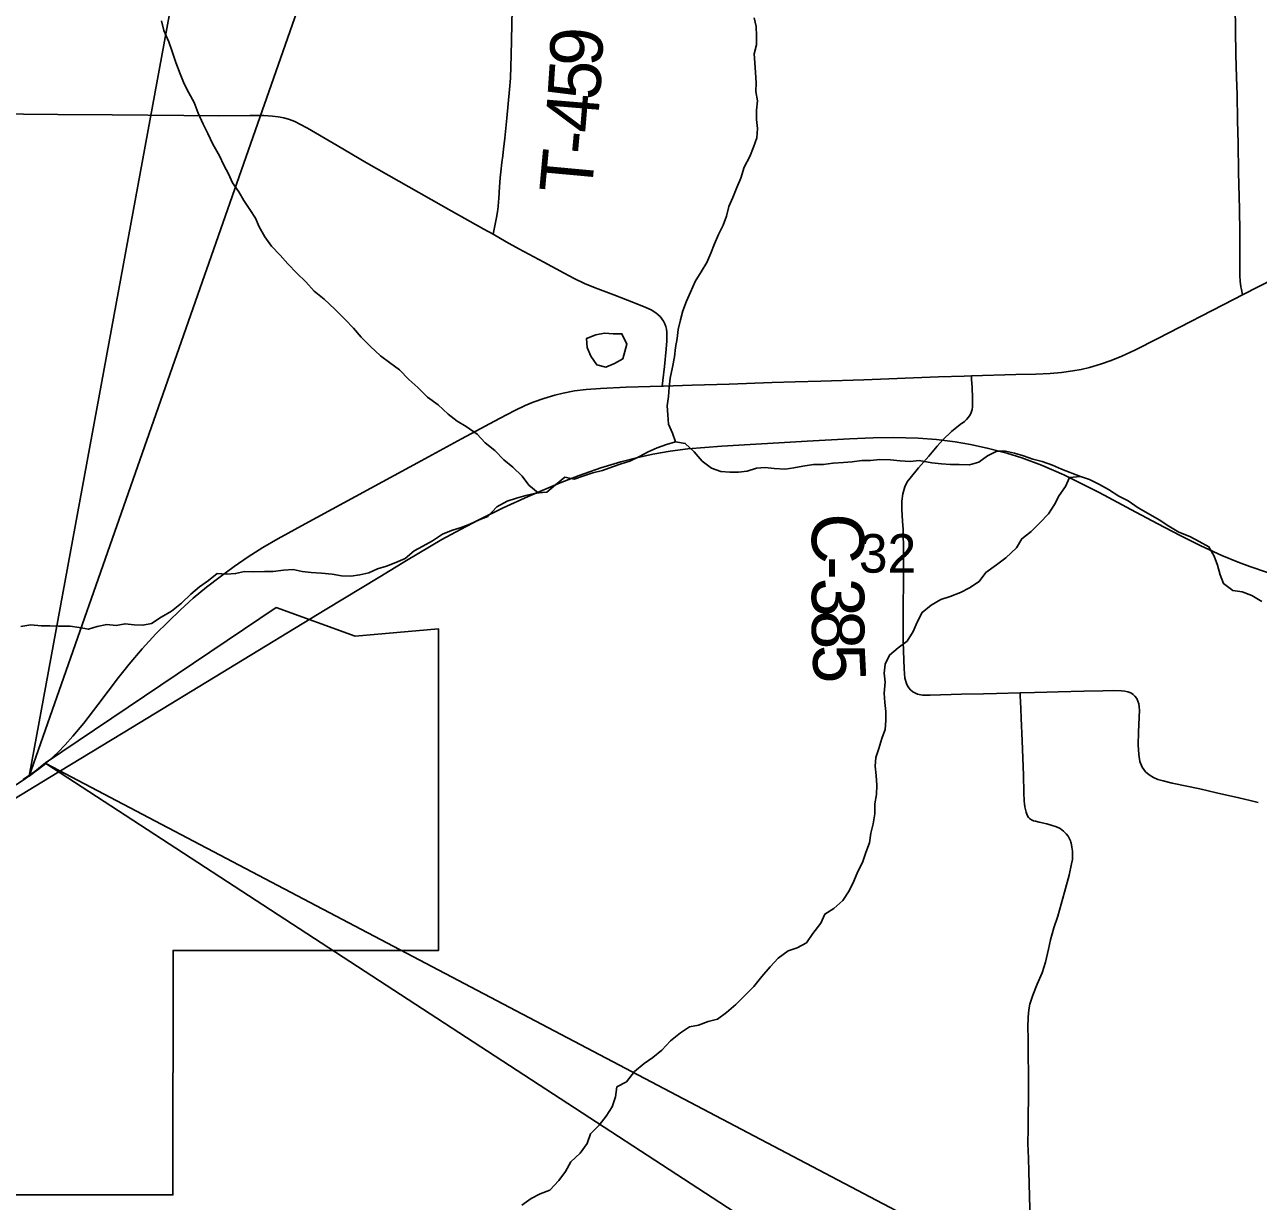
# Model space of a CAD drawing. Extents: x -7.5 to 53.5, y 0 to 22.
# Drawn here: x 5.246 to 6.583, y 17.086 to 18.362 of the extents above; entities that cross this region are included whole.
import ezdxf

# ---------------------------------------------------------------- set-up
doc = ezdxf.new("R2010")
doc.units = 0
for name, color, linetype in [('GM_X_Corporation', 7, 'Continuous'), ('GM_X_County_Road', 7, 'Continuous'), ('GM_X_County_Road_Text', 7, 'Continuous'), ('GM_X_Minor_Lake', 7, 'Continuous'), ('GM_X_Minor_River', 7, 'Continuous'), ('GM_X_Rail_Line', 7, 'Continuous'), ('GM_X_Section_Text', 7, 'Continuous'), ('GM_X_State_Route', 7, 'Continuous'), ('GM_X_Township_Road', 7, 'Continuous'), ('GM_X_Township_Road_Text', 7, 'Continuous'), ('SH_Data', 7, 'Continuous'), ('SH_Text', 7, 'Continuous')]:
    doc.layers.add(name, color=color, linetype=linetype)

msp = doc.modelspace()

# ---------------------------------------------------------------- linework, layer by layer
at = {"layer": 'GM_X_Corporation'}
msp.add_lwpolyline([(5.244, 17.5434), (5.2567, 17.5523), (5.2607, 17.5554), (5.2684, 17.5616), (5.5185, 17.73), (5.6039, 17.6989), (5.6945, 17.7068), (5.6945, 17.3582), (5.4066, 17.3583), (5.4065, 17.093), (5.1262, 17.0931)], dxfattribs=at)
at = {"layer": 'GM_X_County_Road'}
for points in [[(6.2722, 17.9813), (6.2724, 17.9775), (6.2729, 17.9691), (6.2734, 17.9571), (6.2734, 17.9508), (6.2733, 17.9477), (6.2728, 17.9447), (6.272, 17.9417), (6.2707, 17.9389), (6.269, 17.9364), (6.267, 17.934), (6.2648, 17.9317), (6.2599, 17.9284), (6.2506, 17.9211), (6.2413, 17.912), (6.2352, 17.9049), (6.226, 17.8942), (6.2149, 17.8815), (6.2057, 17.8705), (6.2025, 17.8664), (6.1998, 17.8611), (6.1977, 17.8532), (6.1969, 17.8454), (6.1969, 17.8365), (6.1974, 17.8238), (6.198, 17.8147), (6.1983, 17.8058), (6.1985, 17.7999), (6.1986, 17.7935), (6.1987, 17.7825), (6.1986, 17.7682), (6.1984, 17.7536), (6.1982, 17.7356), (6.198, 17.7181), (6.1982, 17.6928), (6.1992, 17.6636), (6.1999, 17.6536), (6.2016, 17.6477), (6.2029, 17.6452), (6.2044, 17.6429), (6.2061, 17.6409), (6.2087, 17.6386), (6.2138, 17.636), (6.219, 17.6352), (6.2274, 17.6349), (6.2614, 17.6362), (6.2851, 17.6366), (6.2992, 17.6369), (6.3251, 17.6374)], [(6.3251, 17.6374), (6.3407, 17.6378), (6.3539, 17.6382), (6.3662, 17.6385), (6.3942, 17.6392), (6.4147, 17.6398), (6.426, 17.6401), (6.4347, 17.6397), (6.4384, 17.6395), (6.4417, 17.6387), (6.4449, 17.6375), (6.4476, 17.6358), (6.4495, 17.634), (6.4514, 17.6313), (6.4527, 17.6286), (6.4537, 17.6257), (6.4541, 17.6224), (6.4543, 17.6188), (6.4539, 17.6112), (6.4532, 17.5948), (6.453, 17.5812), (6.4537, 17.5707), (6.4546, 17.5632), (6.4571, 17.557), (6.461, 17.552), (6.465, 17.5488), (6.4694, 17.5458), (6.4744, 17.5436), (6.4799, 17.542), (6.4899, 17.5397), (6.5197, 17.5334), (6.5378, 17.5292), (6.5621, 17.5237), (6.5742, 17.5209), (6.5832, 17.5188)]]:
    msp.add_lwpolyline(points, dxfattribs=at)
at = {"layer": 'GM_X_Minor_Lake'}
for points in [[(5.8742, 18.0275), (5.8648, 18.0257), (5.8549, 18.022), (5.8555, 18.0121), (5.8596, 18.0026), (5.866, 17.9931), (5.8758, 17.9907), (5.8853, 17.9948), (5.8941, 17.9996)], [(5.8941, 17.9996), (5.8984, 18.0155), (5.8932, 18.027), (5.8837, 18.027), (5.8742, 18.0275)]]:
    msp.add_lwpolyline(points, dxfattribs=at)
at = {"layer": 'GM_X_Minor_River'}
for points in [[(5.3942, 18.3663), (5.3967, 18.3557), (5.4019, 18.3435), (5.4056, 18.3329), (5.4097, 18.3211), (5.4142, 18.3089), (5.4186, 18.2979), (5.4238, 18.2883), (5.4294, 18.2777), (5.4339, 18.2662), (5.4391, 18.2541), (5.4443, 18.2441), (5.4499, 18.2327), (5.457, 18.2198), (5.4615, 18.2099), (5.4667, 18.2003), (5.4712, 18.1908), (5.4779, 18.1809), (5.4835, 18.1714), (5.4899, 18.1618), (5.4959, 18.1523), (5.5, 18.1428), (5.5063, 18.1321), (5.5134, 18.1218), (5.5228, 18.1122), (5.5311, 18.1027), (5.5409, 18.0927), (5.5506, 18.0832)], [(5.9514, 17.9096), (5.948, 17.9191), (5.9439, 17.929), (5.9429, 17.9389), (5.9422, 17.9488), (5.9438, 17.959), (5.9446, 17.9692), (5.9455, 17.9787), (5.9482, 17.9908), (5.9502, 18.0018), (5.9514, 18.012), (5.953, 18.0219), (5.9543, 18.0317), (5.9566, 18.0419), (5.9594, 18.0518), (5.9632, 18.0624), (5.9675, 18.0722), (5.9725, 18.0835), (5.979, 18.0941), (5.9852, 18.1042), (5.9898, 18.1144), (5.9937, 18.1243), (5.9979, 18.1345), (6.003, 18.1447), (6.0068, 18.1545), (6.0092, 18.1651), (6.0134, 18.1749), (6.0177, 18.1855), (6.0223, 18.1957), (6.0258, 18.2078), (6.032, 18.2191), (6.0359, 18.2293), (6.0394, 18.2395), (6.0402, 18.2497), (6.0392, 18.2592), (6.0392, 18.2695), (6.0401, 18.2797), (6.0386, 18.2896), (6.0387, 18.2991), (6.0381, 18.3104), (6.0374, 18.3207), (6.0367, 18.3306), (6.0391, 18.3404), (6.0391, 18.3499), (6.0389, 18.3601), (6.0367, 18.3696)], [(5.5506, 18.0832), (5.5597, 18.0732), (5.5706, 18.0644), (5.5819, 18.0537), (5.5931, 18.0426), (5.6021, 18.033), (5.6104, 18.0231), (5.6202, 18.0135), (5.6315, 18.0032), (5.6413, 17.9959), (5.6522, 17.9878), (5.6623, 17.9775), (5.6721, 17.9687), (5.6826, 17.9583), (5.6939, 17.9499), (5.7049, 17.9399), (5.7146, 17.9323), (5.7245, 17.9265), (5.7365, 17.918), (5.7451, 17.9085), (5.7553, 17.9004), (5.7651, 17.8901), (5.7749, 17.8824), (5.785, 17.8725), (5.7922, 17.8629), (5.8023, 17.8545), (5.8118, 17.8552), (5.8213, 17.863), (5.8313, 17.8713), (5.8415, 17.8693), (5.8521, 17.873), (5.8616, 17.8763), (5.8723, 17.8785), (5.8829, 17.8826), (5.8924, 17.8859), (5.9019, 17.8888), (5.9122, 17.8937), (5.9217, 17.8989), (5.9316, 17.9034), (5.9415, 17.9067), (5.9514, 17.9096), (5.962, 17.908), (5.9717, 17.8988), (5.9804, 17.8889), (5.9905, 17.8812), (6.0004, 17.8777), (6.0102, 17.8769), (6.0197, 17.8768), (6.0292, 17.8778), (6.0391, 17.8812), (6.0485, 17.8818), (6.0584, 17.881), (6.0701, 17.8801), (6.0796, 17.8815), (6.0895, 17.8834), (6.1009, 17.8851), (6.1115, 17.885), (6.1221, 17.8868), (6.1335, 17.8875), (6.143, 17.8882), (6.1532, 17.8896), (6.1627, 17.8895), (6.1729, 17.8906), (6.1843, 17.8901), (6.1949, 17.8892), (6.2059, 17.8884), (6.2154, 17.8894), (6.2294, 17.887), (6.2396, 17.8858), (6.2495, 17.8853), (6.2589, 17.8852), (6.2699, 17.8847), (6.2802, 17.8877), (6.2897, 17.8944), (6.2996, 17.8996), (6.3091, 17.8996), (6.3189, 17.8976), (6.3287, 17.8945), (6.3386, 17.8909), (6.3488, 17.8886), (6.3601, 17.8843), (6.3699, 17.88), (6.3903, 17.8723), (6.4002, 17.8688), (6.4111, 17.8634), (6.4209, 17.858), (6.4319, 17.851), (6.4421, 17.8456), (6.453, 17.8383), (6.4639, 17.8322), (6.4756, 17.8252), (6.4862, 17.8183), (6.4971, 17.8118), (6.5088, 17.8071), (6.519, 17.8017), (6.5296, 17.7959), (6.5352, 17.7856), (6.5389, 17.7761), (6.5418, 17.7655), (6.5455, 17.756), (6.5557, 17.7487)], [(6.3903, 17.8723), (6.3786, 17.8712), (6.374, 17.8614), (6.3674, 17.8516), (6.3624, 17.8418), (6.3559, 17.8316), (6.3463, 17.8219), (6.3368, 17.8125), (6.3269, 17.8046), (6.3211, 17.7948), (6.3093, 17.7839), (6.2993, 17.7764), (6.2879, 17.7682), (6.2806, 17.7584), (6.2699, 17.7513), (6.2604, 17.7464), (6.249, 17.742), (6.2391, 17.7386), (6.2285, 17.7327), (6.2186, 17.7248), (6.2135, 17.7142), (6.2089, 17.704), (6.2024, 17.6935), (6.1928, 17.6864), (6.1833, 17.6785), (6.1787, 17.6687), (6.1775, 17.6588), (6.1785, 17.6493), (6.1777, 17.6372), (6.1783, 17.627), (6.1794, 17.6175), (6.1793, 17.6076), (6.1785, 17.5977), (6.175, 17.5879), (6.1719, 17.5773), (6.1687, 17.5675), (6.1679, 17.558), (6.169, 17.5478), (6.1696, 17.5375), (6.1692, 17.5273), (6.1676, 17.5171), (6.1675, 17.5065), (6.1655, 17.4955), (6.1631, 17.4853), (6.1615, 17.475), (6.1577, 17.4645), (6.1542, 17.4535), (6.1491, 17.4437), (6.1445, 17.4335), (6.1395, 17.4229), (6.1326, 17.4123), (6.123, 17.4037), (6.1131, 17.3977), (6.1089, 17.3879), (6.1004, 17.3766), (6.0932, 17.3664), (6.0833, 17.3612), (6.0734, 17.3579), (6.0627, 17.35), (6.0539, 17.3403), (6.0451, 17.3301), (6.0363, 17.3192), (6.0267, 17.3098), (6.0168, 17.2996), (6.0065, 17.291), (5.997, 17.2835), (5.9867, 17.2813), (5.9764, 17.2772), (5.9666, 17.2754), (5.9567, 17.2687), (5.946, 17.2601), (5.9364, 17.2499), (5.9269, 17.2421), (5.9173, 17.2357), (5.907, 17.2271), (5.8982, 17.2158), (5.8879, 17.2102), (5.8863, 17.1996), (5.8825, 17.1886), (5.8763, 17.1784), (5.8687, 17.1686), (5.8591, 17.1592), (5.8556, 17.149), (5.8479, 17.1385), (5.838, 17.1291), (5.8322, 17.1185), (5.825, 17.1087), (5.815, 17.0982), (5.8047, 17.0941), (5.7948, 17.0893), (5.7846, 17.0818)], [(5.3243, 17.7094), (5.3349, 17.7116), (5.3448, 17.7107), (5.3546, 17.7125), (5.3645, 17.7113), (5.374, 17.7108), (5.3834, 17.7127), (5.3937, 17.7198), (5.4048, 17.7261), (5.4158, 17.7347), (5.4258, 17.7445), (5.4353, 17.7524), (5.4449, 17.7595), (5.4544, 17.767), (5.4646, 17.7661), (5.4745, 17.7668), (5.484, 17.769), (5.4942, 17.7689), (5.5056, 17.7692), (5.5151, 17.7691), (5.5264, 17.7705), (5.5367, 17.7712), (5.5465, 17.7692), (5.5564, 17.768), (5.5677, 17.7675), (5.5791, 17.7662), (5.5893, 17.7643), (5.5992, 17.7642), (5.609, 17.7656), (5.6189, 17.7678), (5.6284, 17.7719), (5.6379, 17.7748), (5.6482, 17.7789), (5.6581, 17.7834), (5.668, 17.7916), (5.6775, 17.7965), (5.6878, 17.8024), (5.6988, 17.8095), (5.7084, 17.8136), (5.719, 17.8169), (5.7285, 17.8203), (5.7384, 17.8251), (5.7479, 17.8288), (5.7575, 17.8393), (5.7689, 17.8453), (5.7788, 17.8486), (5.789, 17.8516), (5.7985, 17.8538), (5.8061, 17.8548)], [(6.5557, 17.7487), (6.5656, 17.7471), (6.5761, 17.7432), (6.5871, 17.7366)], [(5.2417, 17.7094), (5.2523, 17.7112), (5.2637, 17.7103), (5.2731, 17.7102), (5.2826, 17.7098), (5.2951, 17.7097), (5.305, 17.7084), (5.3148, 17.7065), (5.3243, 17.7094)]]:
    msp.add_lwpolyline(points, dxfattribs=at)
at = {"layer": 'GM_X_Rail_Line'}
msp.add_lwpolyline([(5.0726, 17.4239), (5.2728, 17.5456), (5.3626, 17.6002), (5.5716, 17.7275), (5.6308, 17.7635), (5.6598, 17.7812), (5.698, 17.8037), (5.7184, 17.8148), (5.738, 17.8252), (5.7644, 17.8382), (5.7916, 17.8505), (5.8262, 17.8653), (5.8469, 17.8731), (5.8704, 17.8814), (5.892, 17.8881), (5.9092, 17.8924), (5.9269, 17.8964), (5.9454, 17.8996), (5.9647, 17.9022), (6.0014, 17.9052), (6.0942, 17.9105), (6.1399, 17.9131), (6.1656, 17.9142), (6.1876, 17.9146), (6.2144, 17.9138), (6.2343, 17.9123), (6.2544, 17.9096), (6.271, 17.9069), (6.2894, 17.9029), (6.3104, 17.8975), (6.3268, 17.8923), (6.3481, 17.8843), (6.3724, 17.8739), (6.4108, 17.8548), (6.4505, 17.8335), (6.4741, 17.8209), (6.4985, 17.8082), (6.521, 17.7968), (6.5435, 17.7866), (6.5612, 17.7794), (6.5739, 17.7745), (6.593, 17.7682)], dxfattribs=at)
at = {"layer": 'GM_X_State_Route'}
for points in [[(5.2686, 17.561), (5.2817, 17.573), (5.2898, 17.5812), (5.298, 17.5904), (5.3098, 17.6048), (5.325, 17.6245), (5.3475, 17.6543), (5.3591, 17.6688), (5.3733, 17.6854), (5.3881, 17.7014), (5.4012, 17.7147), (5.4147, 17.7276), (5.4286, 17.7401), (5.4429, 17.752), (5.4577, 17.7635), (5.4728, 17.7745), (5.4882, 17.7851), (5.504, 17.7951), (5.5201, 17.8045), (5.55, 17.821), (5.6757, 17.8891), (5.7193, 17.913), (5.7604, 17.9352), (5.777, 17.9437), (5.7883, 17.949), (5.7969, 17.9526), (5.8086, 17.9568), (5.8206, 17.9604), (5.8297, 17.9626), (5.842, 17.9649), (5.8544, 17.9665), (5.8699, 17.9677), (5.8979, 17.969), (5.9368, 17.9702), (5.9383, 17.9702), (5.9693, 17.9712), (6.0097, 17.9723), (6.0562, 17.9742), (6.081, 17.975), (6.109, 17.9757), (6.1556, 17.9771), (6.2363, 17.9801), (6.2643, 17.9811), (6.2722, 17.9813), (6.3202, 17.9826), (6.3419, 17.9832), (6.3574, 17.9839), (6.3698, 17.985), (6.382, 17.9866), (6.3911, 17.9883), (6.4001, 17.9905), (6.412, 17.994), (6.4237, 17.9981), (6.4352, 18.0027), (6.4493, 18.0091), (6.4742, 18.0217), (6.5571, 18.0644), (6.566, 18.069), (6.6539, 18.1141)], [(5.0537, 17.4423), (5.0642, 17.4464), (5.0978, 17.4596), (5.112, 17.4659), (5.1289, 17.474), (5.1454, 17.4828), (5.1644, 17.4936), (5.1873, 17.5074), (5.2019, 17.5162), (5.2285, 17.5326), (5.2442, 17.5428), (5.2569, 17.5518), (5.2609, 17.5548), (5.2686, 17.561)]]:
    msp.add_lwpolyline(points, dxfattribs=at)
at = {"layer": 'GM_X_Township_Road'}
for points in [[(5.7536, 18.1351), (5.7573, 18.1529), (5.7584, 18.1593), (5.7591, 18.1649), (5.7595, 18.1699), (5.7597, 18.1735), (5.7607, 18.1863), (5.7614, 18.1962), (5.762, 18.2024), (5.7632, 18.2126), (5.764, 18.2199), (5.7649, 18.2276), (5.7656, 18.2329), (5.7662, 18.2391), (5.7684, 18.2608), (5.7715, 18.2917), (5.7724, 18.3041), (5.7733, 18.329), (5.7743, 18.3787)], [(6.566, 18.069), (6.5648, 18.0749), (6.5642, 18.0779), (6.5635, 18.0841), (6.5633, 18.0899), (6.5633, 18.0965), (6.5632, 18.137), (6.5627, 18.1619), (6.5618, 18.2023), (6.5614, 18.2334), (6.5608, 18.2583), (6.5601, 18.2863), (6.5596, 18.3049), (6.559, 18.3298), (6.5581, 18.3827)], [(5.1863, 18.2659), (5.2133, 18.2658), (5.2444, 18.2652), (5.2816, 18.2649), (5.3406, 18.2643), (5.4183, 18.2635), (5.4555, 18.2634), (5.4897, 18.2638), (5.5052, 18.2636), (5.5145, 18.263), (5.5207, 18.2622), (5.5268, 18.261), (5.5327, 18.2592), (5.5385, 18.257), (5.5441, 18.2543), (5.5523, 18.2498), (5.5845, 18.2311), (5.6165, 18.2125), (5.6515, 18.1924), (5.7082, 18.1601), (5.7435, 18.1405), (5.7536, 18.1351)], [(5.7536, 18.1351), (5.7678, 18.1267), (5.7814, 18.1192), (5.8087, 18.1046), (5.8305, 18.0926), (5.8415, 18.0868), (5.8527, 18.0815), (5.8641, 18.0767), (5.8845, 18.069), (5.9077, 18.0603), (5.9193, 18.0555), (5.9248, 18.0528), (5.9301, 18.0495), (5.9326, 18.0476), (5.9348, 18.0455), (5.9367, 18.0431), (5.9384, 18.0405), (5.9398, 18.0377), (5.9408, 18.0348), (5.9415, 18.0318), (5.942, 18.0287), (5.9421, 18.0256), (5.942, 18.0194), (5.9414, 18.0101), (5.9395, 17.9915), (5.9376, 17.9761), (5.9368, 17.9702)], [(6.337, 17.0246), (6.3345, 17.1183), (6.3339, 17.1328), (6.3333, 17.1489), (6.3336, 17.1647), (6.3338, 17.1765), (6.3341, 17.2009), (6.3339, 17.22), (6.3337, 17.2489), (6.3336, 17.2631), (6.3335, 17.2748), (6.3337, 17.286), (6.3344, 17.2937), (6.3356, 17.2999), (6.3388, 17.3098), (6.3433, 17.3216), (6.3488, 17.3338), (6.3524, 17.3455), (6.3557, 17.3596), (6.3579, 17.3698), (6.3616, 17.3829), (6.3659, 17.3952), (6.373, 17.4213), (6.378, 17.4398), (6.3808, 17.4523), (6.3816, 17.4568), (6.3818, 17.4609), (6.3816, 17.4657), (6.3812, 17.4703), (6.3807, 17.4728), (6.3802, 17.4745), (6.3799, 17.4757), (6.3794, 17.477), (6.3784, 17.4792), (6.3769, 17.482), (6.375, 17.4845), (6.372, 17.4876), (6.3685, 17.4903), (6.3645, 17.4922), (6.3598, 17.4937), (6.3538, 17.4956), (6.3457, 17.4973), (6.3415, 17.4983), (6.3396, 17.4988), (6.3374, 17.4998), (6.3362, 17.5005), (6.3352, 17.5014), (6.3341, 17.5025), (6.3325, 17.505), (6.3315, 17.508), (6.3307, 17.5111), (6.33, 17.5141), (6.3296, 17.5171), (6.3294, 17.5202), (6.3291, 17.5295), (6.3286, 17.5481), (6.3271, 17.5854), (6.3262, 17.61), (6.3258, 17.6202), (6.3255, 17.6282), (6.3251, 17.6341), (6.3251, 17.6374)]]:
    msp.add_lwpolyline(points, dxfattribs=at)
at = {"layer": 'SH_Data'}
msp.add_line((5.2505, 17.5473), (5.2686, 17.561), dxfattribs=at)
at = {"layer": 'SH_Text'}
for points in [[(5.8885, 19.3693), (5.586, 19.3693), (5.2505, 17.5473)], [(6.8259, 16.7419), (6.5259, 16.7419), (5.2686, 17.561)]]:
    msp.add_lwpolyline(points, close=True, dxfattribs=at)

# ---------------------------------------------------------------- texts
at = {"layer": 'GM_X_County_Road_Text'}
for s, rotation, p in [('C', 270, (6.0991, 17.8323)), ('-', 270.0226, (6.0991, 17.7856)), ('3', 270.1079, (6.0991, 17.7622)), ('8', 270.4142, (6.0991, 17.7269)), ('5', 272.9622, (6.0995, 17.6891))]:
    msp.add_text(s, height=0.0568, rotation=rotation, dxfattribs=at).set_placement(p)
at = {"layer": 'GM_X_Section_Text'}
msp.add_text('32', height=0.04186, rotation=0, dxfattribs=at).set_placement((6.1501, 17.7679))
at = {"layer": 'GM_X_Township_Road_Text'}
for s, rotation, p in [('9', 87.7914, (5.8716, 18.3161)), ('5', 86.1174, (5.8691, 18.2794)), ('4', 85.2836, (5.8662, 18.2436)), ('-', 84.86, (5.8641, 18.2199)), ('T', 84.7427, (5.8602, 18.1774))]:
    msp.add_text(s, height=0.0568, rotation=rotation, dxfattribs=at).set_placement(p)

doc.saveas('drawing.dxf')
